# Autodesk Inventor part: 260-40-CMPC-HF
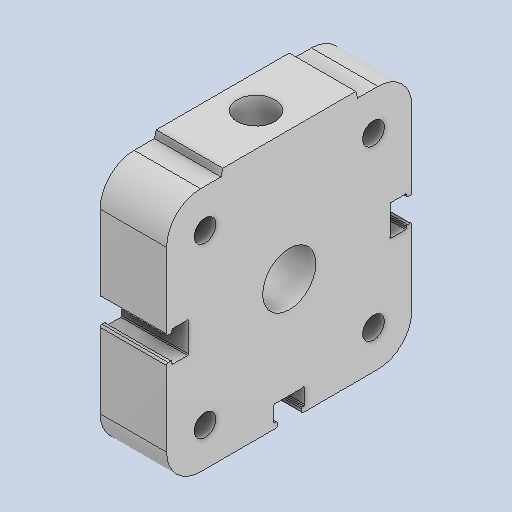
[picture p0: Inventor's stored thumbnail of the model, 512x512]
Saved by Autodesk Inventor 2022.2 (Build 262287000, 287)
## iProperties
Created: 2024-10
Part Number: 260-40-CMPC-HF
Material: Alluminio 6061
Document SubType Name: Modeling
Designer: 18907419
Density: 2.7 g/cm^3
Appearance: Default
Author: 18907419
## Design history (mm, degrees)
feature "Solid1"
node "Solido1"
